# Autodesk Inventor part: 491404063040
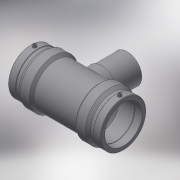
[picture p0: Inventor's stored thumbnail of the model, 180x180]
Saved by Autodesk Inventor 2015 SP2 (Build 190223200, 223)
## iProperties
Created: 2017-06
Part Number: 491404063040
Material: Generic
Description: PLASSON REDUCING TEE 63x40x63
Document SubType Name: Modeling
Designer: KIM
Mass: 367.033 g
Surface Area: 958.44 cm^2
Volume: 367.033 cm^3
Density: 1 g/cm^3
Appearance: Default
Author: KIM
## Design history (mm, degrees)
derived "491404.ipt"
feature "Solid1::491404.ipt"
tag "TaggingFeature1"
body "Solid1"
other parameters: "d0" = 167, "d1" = 63, "d2" = 82, "d3" = 58, "d4" = 33.4, "d5" = 73.8, "d6" = 59.85, "d7" = 63, "d8" = 168 deg, "d10" = 23.2, "d11" = 7.73333, "d13" = 167, "d14" = 17.6296, "d17" = 56.7, "d18" = 63, "d19" = 3.52592, "d20" = 168 deg, "d22" = 76.26, "d23" = 82, "d25" = 135 deg, "d26" = 116.9, "d29" = 58, "d30" = 15, "d31" = 66.8, "d34" = 5 deg, "d35" = 15, "d39" = 5 deg, "d41" = 4, "d42" = 14, "d43" = 0, "d45" = 4, "d46" = 6, "d47" = 0, "d48" = -104, "d51" = 0, "d52" = 32, "d54" = 0, "d55" = 73.8, "d56" = 82, "d57" = 58.45, "d58" = 135 deg, "d59" = 58, "d60" = 58, "d61" = 135 deg, "d62" = 104, "d72" = 75.985, "d73" = 37.9925, "d74" = -104, "d75" = 42, "d77" = 0, "d78" = 32, "d80" = 0, "d82" = 63, "d83" = 0, "d84" = 3, "d85" = 0, "d86" = 19.33333, "d87" = 74.7348, "d88" = 7.73333, "d89" = 3, "d90" = 0, "d_" = 63, "L_" = 167, "L_1" = 58, "D_" = 82, "A_" = 58, "d_2" = 12, "H_" = 104
